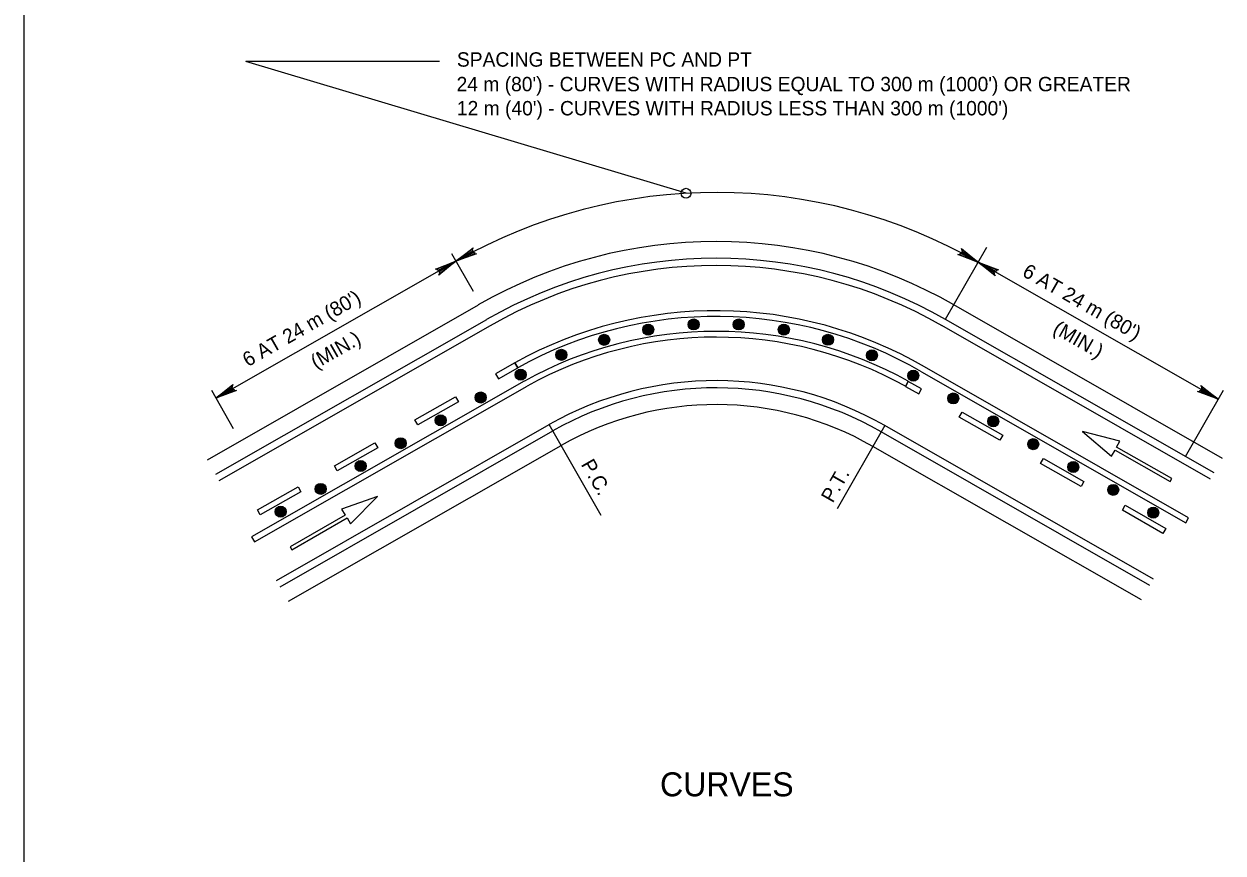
# Model space of a CAD drawing. Extents: x 639362 to 641108, y 298458 to 299646.
# Drawn here: x 640243.3 to 640493.4, y 299239.5 to 299412.4 of the extents above; entities that cross this region are included whole.
import ezdxf

# ---------------------------------------------------------------- set-up
doc = ezdxf.new("R2010")
doc.units = 0
doc.layers.add('1', color=7, linetype='Continuous')
doc.layers.add('2', color=7, linetype='Continuous')

msp = doc.modelspace()

# ---------------------------------------------------------------- linework, layer by layer
at = {"layer": '1'}
msp.add_line((640243.31, 299630.63), (640243.31, 299066.63), dxfattribs=at)
at = {"layer": '2'}
for p, q in [((640381.38, 299377.13), (640289.61, 299404.63)), ((640329.99, 299404.63), (640289.61, 299404.63)), ((640332.47, 299364.56), (640336.97, 299356.69)), ((640444.02, 299365.8), (640435.45, 299350.79)), ((640283.34, 299334.37), (640333.39, 299362.97)), ((640492.33, 299334.17), (640442.29, 299362.76)), ((640281.57, 299321.57), (640338.1, 299353.88)), ((640493.27, 299321.84), (640437.21, 299353.88)), ((640283.3, 299318.53), (640339.84, 299350.84)), ((640284.05, 299317.23), (640340.58, 299349.53)), ((640490.79, 299317.5), (640434.73, 299349.53)), ((640491.54, 299318.8), (640435.47, 299350.84)), ((640345.71, 299341.8), (640341.64, 299339.48)), ((640346.29, 299340.75), (640345.71, 299341.8)), ((640345.71, 299341.8), (640346.29, 299340.75)), ((640345.71, 299341.8), (640346.29, 299340.75)), ((640341.64, 299339.48), (640342.24, 299338.43)), ((640342.24, 299338.43), (640346.29, 299340.75)), ((640430.51, 299339.9), (640485.6, 299308.42)), ((640486.2, 299309.46), (640431.11, 299340.94)), ((640347.66, 299337.96), (640290.78, 299305.46)), ((640291.37, 299304.41), (640348.26, 299336.92)), ((640427.73, 299337.91), (640427.14, 299336.87)), ((640427.14, 299336.87), (640427.73, 299337.91)), ((640427.14, 299336.87), (640429.91, 299335.29)), ((640430.5, 299336.33), (640427.73, 299337.91)), ((640429.91, 299335.29), (640430.5, 299336.33)), ((640282.39, 299336.04), (640286.93, 299328.09)), ((640324.85, 299329.88), (640333.31, 299334.71)), ((640333.91, 299333.67), (640325.44, 299328.84)), ((640333.31, 299334.71), (640333.91, 299333.67)), ((640493.37, 299336), (640485.47, 299322.17)), ((640438.37, 299330.45), (640438.96, 299331.5)), ((640438.96, 299331.5), (640447.43, 299326.66)), ((640295.97, 299296.37), (640352.85, 299328.88)), ((640325.44, 299328.84), (640324.85, 299329.88)), ((640363.69, 299309.92), (640352.85, 299328.88)), ((640422.82, 299328.68), (640412.91, 299311.35)), ((640478.88, 299296.65), (640422.82, 299328.68)), ((640446.83, 299325.62), (640438.37, 299330.45)), ((640296.71, 299295.07), (640353.6, 299327.58)), ((640478.13, 299295.35), (640422.07, 299327.38)), ((640447.43, 299326.66), (640446.83, 299325.62)), ((640464.08, 299327.42), (640470.14, 299322.29)), ((640471.84, 299325.46), (640464.08, 299327.42)), ((640298.45, 299292.03), (640355.33, 299324.54)), ((640308.05, 299320.28), (640316.51, 299325.12)), ((640317.11, 299324.07), (640308.65, 299319.24)), ((640316.51, 299325.12), (640317.11, 299324.07)), ((640476.4, 299292.31), (640420.34, 299324.34)), ((640471.13, 299324.2), (640471.84, 299325.46)), ((640482.73, 299317.64), (640471.13, 299324.2)), ((640455.3, 299320.8), (640455.9, 299321.84)), ((640455.9, 299321.84), (640464.36, 299317)), ((640470.14, 299322.29), (640470.86, 299323.55)), ((640470.86, 299323.55), (640482.38, 299317.03)), ((640308.65, 299319.24), (640308.05, 299320.28)), ((640463.77, 299315.96), (640455.3, 299320.8)), ((640464.36, 299317), (640463.77, 299315.96)), ((640482.38, 299317.03), (640482.73, 299317.64)), ((640291.99, 299311.1), (640300.46, 299315.94)), ((640301.05, 299314.9), (640292.59, 299310.06)), ((640300.46, 299315.94), (640301.05, 299314.9)), ((640317.04, 299313.9), (640309.55, 299311.27)), ((640311.42, 299308.2), (640317.04, 299313.9)), ((640292.59, 299310.06), (640291.99, 299311.1)), ((640309.55, 299311.27), (640310.27, 299310.02)), ((640472.38, 299311.02), (640472.98, 299312.06)), ((640472.98, 299312.06), (640481.44, 299307.23)), ((640310.27, 299310.02), (640298.81, 299303.38)), ((640299.17, 299302.77), (640310.7, 299309.45)), ((640310.7, 299309.45), (640311.42, 299308.2)), ((640480.85, 299306.18), (640472.38, 299311.02)), ((640485.6, 299308.42), (640486.2, 299309.46)), ((640481.44, 299307.23), (640480.85, 299306.18)), ((640290.78, 299305.46), (640291.37, 299304.41)), ((640298.81, 299303.38), (640299.17, 299302.77))]:
    msp.add_line(p, q, dxfattribs=at)
for points in [[(640337.39, 299364.56), (640337.1, 299364.76), (640333.39, 299362.97), (640337.39, 299364.56), (640337.68, 299364.5), (640333.39, 299362.97), (640336.89, 299365.13), (640336.88, 299365.47), (640333.39, 299362.97), (640336.98, 299365.77), (640336.88, 299365.47)], [(640438.92, 299365.32), (640438.9, 299364.97), (640442.36, 299362.73), (640438.92, 299365.32), (640438.82, 299365.59), (640442.36, 299362.73), (640438.69, 299364.59), (640438.41, 299364.4), (640442.36, 299362.73), (640438.1, 299364.34), (640438.41, 299364.4)], [(640329.41, 299361.28), (640329.71, 299361.09), (640333.39, 299362.97), (640329.41, 299361.28), (640329.13, 299361.33), (640333.39, 299362.97), (640329.93, 299360.72), (640329.95, 299360.38), (640333.39, 299362.97), (640329.85, 299360.09), (640329.95, 299360.38)], [(640445.74, 299360.17), (640445.75, 299360.52), (640442.29, 299362.76), (640445.74, 299360.17), (640445.83, 299359.9), (640442.29, 299362.76), (640445.96, 299360.89), (640446.25, 299361.08), (640442.29, 299362.76), (640446.55, 299361.15), (640446.25, 299361.08)], [(640287.32, 299336.04), (640287.03, 299336.23), (640283.34, 299334.37), (640287.32, 299336.04), (640287.61, 299335.99), (640283.34, 299334.37), (640286.81, 299336.6), (640286.79, 299336.95), (640283.34, 299334.37), (640286.89, 299337.24), (640286.79, 299336.95)], [(640488.88, 299336.76), (640488.86, 299336.41), (640492.33, 299334.17), (640488.88, 299336.76), (640488.78, 299337.03), (640492.33, 299334.17), (640488.65, 299336.03), (640488.37, 299335.84), (640492.33, 299334.17), (640488.06, 299335.78), (640488.37, 299335.84)]]:
    msp.add_lwpolyline(points, dxfattribs=at)
for centre, radius in [((640381.38, 299377.13), 1.04), ((640373.49, 299348.69), 1.15), ((640373.49, 299348.69), 1.07), ((640373.49, 299348.69), 0.985), ((640373.49, 299348.69), 0.904), ((640373.49, 299348.69), 0.822), ((640373.49, 299348.69), 0.741), ((640373.49, 299348.69), 0.659), ((640373.49, 299348.69), 0.578), ((640373.49, 299348.69), 0.496), ((640373.49, 299348.69), 0.414), ((640373.49, 299348.69), 0.333), ((640373.49, 299348.69), 0.251), ((640373.49, 299348.69), 0.17), ((640373.49, 299348.69), 0.0881), ((640382.98, 299349.77), 1.15), ((640382.98, 299349.77), 1.07), ((640382.98, 299349.77), 0.985), ((640382.98, 299349.77), 0.904), ((640382.98, 299349.77), 0.822), ((640382.98, 299349.77), 0.741), ((640382.98, 299349.77), 0.659), ((640382.98, 299349.77), 0.578), ((640382.98, 299349.77), 0.496), ((640382.98, 299349.77), 0.414), ((640382.98, 299349.77), 0.333), ((640382.98, 299349.77), 0.251), ((640382.98, 299349.77), 0.17), ((640382.98, 299349.77), 0.0881), ((640392.37, 299349.77), 1.15), ((640392.37, 299349.77), 1.07), ((640392.37, 299349.77), 0.985), ((640392.37, 299349.77), 0.904), ((640392.37, 299349.77), 0.822), ((640392.37, 299349.77), 0.741), ((640392.37, 299349.77), 0.659), ((640392.37, 299349.77), 0.578), ((640392.37, 299349.77), 0.496), ((640392.37, 299349.77), 0.414), ((640392.37, 299349.77), 0.333), ((640392.37, 299349.77), 0.251), ((640392.37, 299349.77), 0.17), ((640392.37, 299349.77), 0.0881), ((640401.78, 299348.7), 1.15), ((640401.78, 299348.7), 1.07), ((640401.78, 299348.7), 0.985), ((640401.78, 299348.7), 0.904), ((640401.78, 299348.7), 0.822), ((640401.78, 299348.7), 0.741), ((640401.78, 299348.7), 0.659), ((640401.78, 299348.7), 0.578), ((640401.78, 299348.7), 0.496), ((640401.78, 299348.7), 0.414), ((640401.78, 299348.7), 0.333), ((640401.78, 299348.7), 0.251), ((640401.78, 299348.7), 0.17), ((640401.78, 299348.7), 0.0881), ((640364.31, 299346.57), 1.15), ((640364.31, 299346.57), 1.07), ((640364.31, 299346.57), 0.985), ((640364.31, 299346.57), 0.904), ((640364.31, 299346.57), 0.822), ((640364.31, 299346.57), 0.741), ((640364.31, 299346.57), 0.659), ((640364.31, 299346.57), 0.578), ((640364.31, 299346.57), 0.496), ((640364.31, 299346.57), 0.414), ((640364.31, 299346.57), 0.333), ((640364.31, 299346.57), 0.251), ((640364.31, 299346.57), 0.17), ((640364.31, 299346.57), 0.0881), ((640410.99, 299346.58), 1.15), ((640410.99, 299346.58), 1.07), ((640410.99, 299346.58), 0.985), ((640410.99, 299346.58), 0.904), ((640410.99, 299346.58), 0.822), ((640410.99, 299346.58), 0.741), ((640410.99, 299346.58), 0.659), ((640410.99, 299346.58), 0.578), ((640410.99, 299346.58), 0.496), ((640410.99, 299346.58), 0.414), ((640410.99, 299346.58), 0.333), ((640410.99, 299346.58), 0.251), ((640410.99, 299346.58), 0.17), ((640410.99, 299346.58), 0.0881), ((640355.39, 299343.44), 1.15), ((640355.39, 299343.44), 1.07), ((640355.39, 299343.44), 0.985), ((640355.39, 299343.44), 0.904), ((640355.39, 299343.44), 0.822), ((640355.39, 299343.44), 0.741), ((640355.39, 299343.44), 0.659), ((640355.39, 299343.44), 0.578), ((640355.39, 299343.44), 0.496), ((640355.39, 299343.44), 0.414), ((640355.39, 299343.44), 0.333), ((640355.39, 299343.44), 0.251), ((640355.39, 299343.44), 0.17), ((640420.15, 299343.35), 1.15), ((640420.15, 299343.35), 1.07), ((640420.15, 299343.35), 0.985), ((640420.15, 299343.35), 0.904), ((640420.15, 299343.35), 0.822), ((640420.15, 299343.35), 0.741), ((640420.15, 299343.35), 0.659), ((640420.15, 299343.35), 0.578), ((640420.15, 299343.35), 0.496), ((640420.15, 299343.35), 0.414), ((640420.15, 299343.35), 0.333), ((640420.15, 299343.35), 0.251), ((640355.39, 299343.44), 0.0881), ((640420.15, 299343.35), 0.17), ((640420.15, 299343.35), 0.0881), ((640346.9, 299339.31), 1.15), ((640346.9, 299339.31), 1.07), ((640346.9, 299339.31), 0.985), ((640346.9, 299339.31), 0.904), ((640346.9, 299339.31), 0.822), ((640346.9, 299339.31), 0.741), ((640346.9, 299339.31), 0.659), ((640346.9, 299339.31), 0.578), ((640346.9, 299339.31), 0.496), ((640346.9, 299339.31), 0.414), ((640346.9, 299339.31), 0.333), ((640346.9, 299339.31), 0.251), ((640346.9, 299339.31), 0.17), ((640346.9, 299339.31), 0.0881), ((640428.77, 299339.11), 1.15), ((640428.77, 299339.11), 1.07), ((640428.77, 299339.11), 0.985), ((640428.77, 299339.11), 0.904), ((640428.77, 299339.11), 0.822), ((640428.77, 299339.11), 0.741), ((640428.77, 299339.11), 0.659), ((640428.77, 299339.11), 0.578), ((640428.77, 299339.11), 0.496), ((640428.77, 299339.11), 0.414), ((640428.77, 299339.11), 0.333), ((640428.77, 299339.11), 0.251), ((640428.77, 299339.11), 0.17), ((640428.77, 299339.11), 0.0881), ((640338.56, 299334.54), 1.15), ((640338.56, 299334.54), 1.07), ((640338.56, 299334.54), 0.985), ((640338.56, 299334.54), 0.904), ((640338.56, 299334.54), 0.822), ((640338.56, 299334.54), 0.741), ((640338.56, 299334.54), 0.659), ((640338.56, 299334.54), 0.578), ((640338.56, 299334.54), 0.496), ((640338.56, 299334.54), 0.414), ((640338.56, 299334.54), 0.333), ((640338.56, 299334.54), 0.251), ((640338.56, 299334.54), 0.17), ((640338.56, 299334.54), 0.0881), ((640437.11, 299334.34), 1.15), ((640437.11, 299334.34), 1.07), ((640437.11, 299334.34), 0.985), ((640437.11, 299334.34), 0.904), ((640437.11, 299334.34), 0.822), ((640437.11, 299334.34), 0.741), ((640437.11, 299334.34), 0.659), ((640437.11, 299334.34), 0.578), ((640437.11, 299334.34), 0.496), ((640437.11, 299334.34), 0.414), ((640437.11, 299334.34), 0.333), ((640437.11, 299334.34), 0.251), ((640437.11, 299334.34), 0.17), ((640437.11, 299334.34), 0.0881), ((640330.22, 299329.78), 1.15), ((640330.22, 299329.78), 1.07), ((640330.22, 299329.78), 0.985), ((640330.22, 299329.78), 0.904), ((640330.22, 299329.78), 0.822), ((640330.22, 299329.78), 0.741), ((640330.22, 299329.78), 0.659), ((640330.22, 299329.78), 0.578), ((640330.22, 299329.78), 0.496), ((640330.22, 299329.78), 0.414), ((640330.22, 299329.78), 0.333), ((640330.22, 299329.78), 0.251), ((640330.22, 299329.78), 0.17), ((640330.22, 299329.78), 0.0881), ((640445.45, 299329.57), 1.15), ((640445.45, 299329.57), 1.07), ((640445.45, 299329.57), 0.985), ((640445.45, 299329.57), 0.904), ((640445.45, 299329.57), 0.822), ((640445.45, 299329.57), 0.741), ((640445.45, 299329.57), 0.659), ((640445.45, 299329.57), 0.578), ((640445.45, 299329.57), 0.496), ((640445.45, 299329.57), 0.414), ((640445.45, 299329.57), 0.333), ((640445.45, 299329.57), 0.251), ((640445.45, 299329.57), 0.17), ((640445.45, 299329.57), 0.0881), ((640321.88, 299325.01), 1.15), ((640321.88, 299325.01), 1.07), ((640321.88, 299325.01), 0.985), ((640321.88, 299325.01), 0.904), ((640321.88, 299325.01), 0.822), ((640321.88, 299325.01), 0.741), ((640321.88, 299325.01), 0.659), ((640321.88, 299325.01), 0.578), ((640321.88, 299325.01), 0.496), ((640321.88, 299325.01), 0.414), ((640321.88, 299325.01), 0.333), ((640321.88, 299325.01), 0.251), ((640321.88, 299325.01), 0.17), ((640321.88, 299325.01), 0.0881), ((640453.79, 299324.81), 1.15), ((640453.79, 299324.81), 1.07), ((640453.79, 299324.81), 0.985), ((640453.79, 299324.81), 0.904), ((640453.79, 299324.81), 0.822), ((640453.79, 299324.81), 0.741), ((640453.79, 299324.81), 0.659), ((640453.79, 299324.81), 0.578), ((640453.79, 299324.81), 0.496), ((640453.79, 299324.81), 0.414), ((640453.79, 299324.81), 0.333), ((640453.79, 299324.81), 0.251), ((640453.79, 299324.81), 0.17), ((640453.79, 299324.81), 0.0881), ((640313.54, 299320.25), 1.15), ((640313.54, 299320.25), 1.07), ((640313.54, 299320.25), 0.985), ((640313.54, 299320.25), 0.904), ((640313.54, 299320.25), 0.822), ((640462.13, 299320.04), 1.15), ((640462.13, 299320.04), 1.07), ((640313.54, 299320.25), 0.741), ((640313.54, 299320.25), 0.659), ((640313.54, 299320.25), 0.578), ((640313.54, 299320.25), 0.496), ((640313.54, 299320.25), 0.414), ((640313.54, 299320.25), 0.333), ((640313.54, 299320.25), 0.251), ((640313.54, 299320.25), 0.17), ((640313.54, 299320.25), 0.0881), ((640462.13, 299320.04), 0.985), ((640462.13, 299320.04), 0.904), ((640462.13, 299320.04), 0.822), ((640462.13, 299320.04), 0.741), ((640462.13, 299320.04), 0.659), ((640462.13, 299320.04), 0.578), ((640462.13, 299320.04), 0.496), ((640462.13, 299320.04), 0.414), ((640462.13, 299320.04), 0.333), ((640462.13, 299320.04), 0.251), ((640462.13, 299320.04), 0.17), ((640462.13, 299320.04), 0.0881), ((640305.2, 299315.48), 1.15), ((640305.2, 299315.48), 1.07), ((640305.2, 299315.48), 0.985), ((640305.2, 299315.48), 0.904), ((640305.2, 299315.48), 0.822), ((640305.2, 299315.48), 0.741), ((640305.2, 299315.48), 0.659), ((640305.2, 299315.48), 0.578), ((640470.47, 299315.28), 1.15), ((640470.47, 299315.28), 1.07), ((640470.47, 299315.28), 0.985), ((640470.47, 299315.28), 0.904), ((640470.47, 299315.28), 0.822), ((640305.2, 299315.48), 0.496), ((640305.2, 299315.48), 0.414), ((640305.2, 299315.48), 0.333), ((640305.2, 299315.48), 0.251), ((640305.2, 299315.48), 0.17), ((640305.2, 299315.48), 0.0881), ((640470.47, 299315.28), 0.741), ((640470.47, 299315.28), 0.659), ((640470.47, 299315.28), 0.578), ((640470.47, 299315.28), 0.496), ((640470.47, 299315.28), 0.414), ((640470.47, 299315.28), 0.333), ((640470.47, 299315.28), 0.251), ((640470.47, 299315.28), 0.17), ((640470.47, 299315.28), 0.0881), ((640296.86, 299310.72), 1.15), ((640296.86, 299310.72), 1.07), ((640296.86, 299310.72), 0.985), ((640296.86, 299310.72), 0.904), ((640296.86, 299310.72), 0.822), ((640296.86, 299310.72), 0.741), ((640296.86, 299310.72), 0.659), ((640296.86, 299310.72), 0.578), ((640296.86, 299310.72), 0.496), ((640296.86, 299310.72), 0.414), ((640478.81, 299310.51), 1.15), ((640478.81, 299310.51), 1.07), ((640478.81, 299310.51), 0.985), ((640478.81, 299310.51), 0.904), ((640478.81, 299310.51), 0.822), ((640478.81, 299310.51), 0.741), ((640478.81, 299310.51), 0.659), ((640478.81, 299310.51), 0.578), ((640296.86, 299310.72), 0.333), ((640296.86, 299310.72), 0.251), ((640296.86, 299310.72), 0.17), ((640296.86, 299310.72), 0.0881), ((640478.81, 299310.51), 0.496), ((640478.81, 299310.51), 0.414), ((640478.81, 299310.51), 0.333), ((640478.81, 299310.51), 0.251), ((640478.81, 299310.51), 0.17), ((640478.81, 299310.51), 0.0881)]:
    msp.add_circle(centre, radius, dxfattribs=at)
for centre, radius, start, end in [((640387.66, 299267.45), 109.86, 60.1371, 119.6067), ((640387.66, 299267.45), 99.63, 60.1372, 119.8628), ((640387.66, 299267.45), 96.13, 60.1372, 119.8628), ((640387.66, 299267.45), 94.63, 60.1372, 119.8628), ((640387.65, 299266.03), 86.61, 59.8818, 118.9662), ((640387.65, 299266.03), 85.41, 59.8819, 118.9663), ((640387.66, 299266.01), 82.32, 60.8663, 119.0641), ((640387.66, 299266.02), 81.11, 60.8699, 119.0594), ((640387.66, 299267.45), 70.61, 60.1372, 119.5398), ((640387.66, 299267.45), 69.11, 60.1372, 119.5398), ((640387.66, 299267.45), 65.61, 60.1372, 119.5398)]:
    msp.add_arc(centre, radius, start, end, dxfattribs=at)

# ---------------------------------------------------------------- texts
for s, height, p in [('SPACING BETWEEN PC AND PT', 3, (640333.6, 299403.54)), ("24 m (80') - CURVES WITH RADIUS EQUAL TO 300 m (1000') OR GREATER", 3, (640333.53, 299398.41)), ("12 m (40') - CURVES WITH RADIUS LESS THAN 300 m (1000')", 3, (640333.6, 299393.38)), ('CURVES', 5, (640375.96, 299251.36))]:
    msp.add_text(s, height=height, dxfattribs=at).set_placement(p)
for s, rotation, p in [("6 AT 24 m (80')", 330.2559, (640451.29, 299360.02)), ("6 AT 24 m (80')", 29.7453, (640289.99, 299340.85)), ('(MIN.)', 330.2559, (640457.66, 299348.13)), ('(MIN.)', 29.7453, (640304.2, 299340.41)), ('P.C.', 299.7361, (640359.39, 299320.6)), ('P.T.', 60.2574, (640411.97, 299312.38))]:
    msp.add_text(s, height=3, rotation=rotation, dxfattribs=at).set_placement(p)

doc.saveas('drawing.dxf')
